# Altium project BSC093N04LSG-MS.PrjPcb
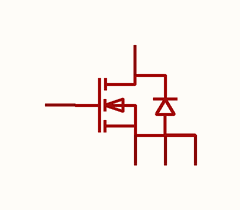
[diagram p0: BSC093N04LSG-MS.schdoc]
1 sheet, 1 parts. Net scope: global (net labels, ports and power ports of the same name join across sheets).

## Sheet BSC093N04LSG-MS.schdoc
size 127 x 101 mm

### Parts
Q?  bsc093n04lsg-ms  [TDSON-8_L5.9-W5.2-P1.27-BL]  (value not drawn)

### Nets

Not connected (* = marked no-connect by the designer): Q? 1(S) 2(S) 3(S) 4(G) 5(D)

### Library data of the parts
Q? = bsc093n04lsg-ms: 数量:1个N沟道;漏源电压(Vdss):40V;连续漏极电流(Id):50A;导通电阻(RDS(on)):14mΩ@10V;耗散功率(Pd):-;阈值电压(Vgs(th)):2.5V;; Manufacturer: MSKSEMI(美森科); AddInBom: yes; ModelId: ff3d8edf19694f3eb1c5df98919f3bc8; ModelTransform: 216.9287,242.5192,0,0,0,0,0,43.307,0; Number: 1个N沟道; Drain to Source Voltage: 40V; Current - Continuous Drain(Id): 50A; Gate Threshold Voltage (Vgs(th)): 2.5V; Gate Charge(Qg): 24nC@10V; Input Capacitance(Ciss): 1.54nF; Reverse Transfer Capacitance (Crss@Vds): 115pF; Type: N沟道; Output Capacitance(Coss): 171pF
